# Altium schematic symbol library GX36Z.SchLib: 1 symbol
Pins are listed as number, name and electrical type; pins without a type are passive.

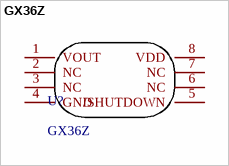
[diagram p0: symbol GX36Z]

## GX36Z
designator U?
footprint SOP8
pins: 1 VOUT, 2 NC, 3 NC, 4 GND, 5 /SHUTDOWN, 6 NC, 7 NC, 8 VDD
